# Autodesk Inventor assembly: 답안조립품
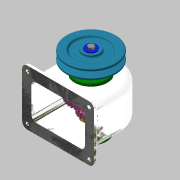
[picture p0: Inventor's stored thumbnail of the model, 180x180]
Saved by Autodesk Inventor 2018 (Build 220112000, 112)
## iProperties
Created: 2022-09
Part Number: 답안조립품
Material: 일반
Document SubType Name: Assembly
Designer: home
Author: home
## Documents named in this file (16)
- C:\Users\home\Desktop\720906V1010\답안조립품.iam
- C:\Users\home\Desktop\720906V1010\본체.ipt
- C:\Users\home\Desktop\720906V1010\축.ipt
- C:\Users\home\Desktop\720906V1010\뒤커버.ipt
- C:\Users\home\Desktop\720906V1010\앞커버.ipt
- C:\Users\home\Desktop\720906V1010\베어링 6203.ipt
- C:\Users\home\Desktop\720906V1010\볼트 M3 x 10.ipt
- C:\Users\home\Desktop\720906V1010\키 6 x 6 x 22.ipt
- C:\Users\home\Desktop\720906V1010\키 5 x 5 x 18.ipt
- C:\Users\home\Desktop\720906V1010\스퍼기어.ipt
- C:\Users\home\Desktop\720906V1010\칼라.ipt
- C:\Users\home\Desktop\720906V1010\오일 실 17 x 30 x 8.ipt
- C:\Users\home\Desktop\720906V1010\멈춤나사 M4 x 10.ipt
- C:\Users\home\Desktop\720906V1010\V-벨트풀리.ipt
- C:\Users\home\Desktop\720906V1010\육각머리볼트 M3 x 8.ipt
- C:\Users\home\Desktop\720906V1010\와셔 6 x 22.ipt
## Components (9 placed, 2 different names)
1. V-벨트풀리:1 — 플러쉬:1
2. ISO 4762 M3 x 10:1
3. ISO 4762 M3 x 10:3
4. ISO 4762 M3 x 10:4
5. ISO 4762 M3 x 10:5
6. ISO 4762 M3 x 10:2
7. ISO 4762 M3 x 10:6
8. ISO 4762 M3 x 10:7
9. ISO 4762 M3 x 10:8
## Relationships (1: Flush 1)
- 플러쉬:1 [Flush]: V-벨트풀리:1
